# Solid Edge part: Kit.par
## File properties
Author: bmolnar
Last saved by: bmolnar
Revision: 76
Sűrűség: 0,000 kg/m^3
Pontosság: 0,990
Username: bmolnar
Dokumentum tartalom típus: 0
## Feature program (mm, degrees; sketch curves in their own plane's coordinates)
base feature "unnamed BaseFeature 1"
sketch for "unnamed Hole 1" plane through (17.575, 12.675, 89.2) normal (0, 0, 1) x-axis (0.38075, -0.924678, 0)
  hole centre (-3.8102, 0.136) bore radius 2.4585
hole "unnamed Hole 1" through
sketch for "unnamed Hole 2" plane through (17.575, 12.675, 89.2) normal (0, 0, 1) x-axis (0.38075, -0.924678, 0)
  hole centre (26.2418, -12.2384) bore radius 2.4585
hole "unnamed Hole 2" through
sketch for "unnamed Hole 3" plane through (17.575, 12.675, 89.2) normal (0, 0, 1) x-axis (0.38075, -0.924678, 0)
  hole centre (-16.1846, -29.9161) bore radius 2.4585
hole "unnamed Hole 3" through
sketch for "unnamed Hole 4" plane through (17.575, 12.675, 89.2) normal (0, 0, 1) x-axis (0.38075, -0.924678, 0)
  hole centre (13.8675, -42.2904) bore radius 2.4585
hole "unnamed Hole 4" through
pattern "unnamed Pattern 1" of "unnamed Hole 1", "unnamed Hole 2", "unnamed Hole 3", "unnamed Hole 4"
thread "unnamed Thread 1"
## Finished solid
Body 1: solid body, 318 faces, 751 edges, 454 vertices, 4 internal voids.
  Faces by surface: plane 145, cylinder 71, swept 55, torus 25, cone 21, spline 1
  Edges by curve: line 433, circle 187, spline 126, curve on surface 4, intersection 1
Bounding box of the edges (mm; curved faces can reach further): 49.000 x 49.000 x 14.100, from (-24.5, -24.5, 79.6) to (24.5, 24.5, 93.7).
Cylindrical faces by radius (mm): R0.2 x30, R0.335 x1, R0.5307 x1, R1.25 x1, R2.4585 x4, R2.5402 x12, R2.6 x4, R3.75 x4, R4 x4, R4.283 x1, R4.5 x4, R6.27 x1, R6.85 x1, R7 x1, R8.16 x1, R8.25 x1
Conical faces (half-angle, radius in mm at the cone's reference point): 0.5 deg R8 x4, 0.5 deg R8.6 x1, 0.5 deg R10.6 x1, 3 deg R8.205 x1, 7 deg R7.5925 x1, 14 deg R6.135 x1, 14 deg R6.4811 x1, 17 deg R6.135 x1, 23 deg R6.829 x1, 42.5 deg R6.1233 x1, 45 deg R2.8085 x4, 45 deg R7 x1, 84 deg R6.4608 x1, 85 deg R7.9463 x1, 87 deg R6.1765 x1
Toroidal faces (ring radius, tube radius in mm): R2.9402 r0.4 x12, R3.55 r0.2 x8, R6.8057 r0.2025 x1, R7.2522 r0.2925 x1, R7.96 r0.2 x1, R9.0957 r0.5 x1, R10.1043 r0.5 x1
Planar faces by outward normal: +x 11, +y 12, +z 21, -x 9, -y 12, -z 3, oblique 77
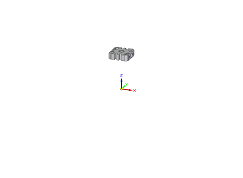
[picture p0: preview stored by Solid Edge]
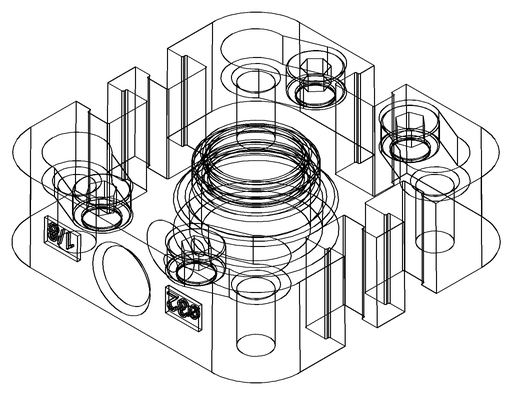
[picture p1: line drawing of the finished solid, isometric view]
